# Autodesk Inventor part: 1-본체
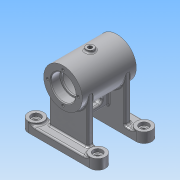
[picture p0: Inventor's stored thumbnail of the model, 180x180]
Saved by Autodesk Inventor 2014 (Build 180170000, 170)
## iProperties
Created: 2015-11
Part Number: 1-본체
Material: 알루미늄 6061
Document SubType Name: Modeling
Designer: 103-23
Density: 2.71 g/cm^3
Appearance: 알루미늄 - 평지
Mass: 358.984 g
Surface Area: 460.1 cm^2
Volume: 132.467 cm^3
Author: 103-23
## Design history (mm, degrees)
sketch "스케치1"
  geometry: L1 (-40, 40)-(40, 40); L2 (40, 20)-(-40, 20); A1 r 10 centre (40, 30) between (40, 20) and (40, 40); A2 r 10 centre (-40, 30) between (-40, 40) and (-40, 20); 1 further point
  constraints: 4 end point, 4 point on circle, 4 tangent, 2 centre point, 1 horizontal, 1 parallel
  dimensions: "d0" = 40 distance from line of L1 point (0, 0); "d1" = 20 distance between parallel lines of L2 L1; "d2" = 80 distance of A1.centre A2.centre; "d3" = 40 horizontal distance of point (0, 0) A2.centre
extrude "돌출1" new body sketch "스케치1" distance "d4" = 10; taper "d5" = 0 deg
node "작업 평면1"
sketch "스케치2"
  geometry: L1 (-35, 68)-(35, 68); L2 (-35, 84)-(-23, 84); L3 (-23, 84)-(-23, 82); L4 (-23, 82)-(-21, 82); L5 (-21, 82)-(-21, 89); L6 (-21, 89)-(21, 89); L7 (21, 89)-(21, 82); L8 (21, 82)-(23, 82); L9 (23, 82)-(23, 84); L10 (23, 84)-(35, 84); L11 (35, 84)-(35, 93); L12 (35, 93)-(-35, 93); L13 (-35, 93)-(-35, 84); 2 further points
  constraints: 26 end point, 10 parallel, 5 collinear, 2 point on line, 1 horizontal, 1 midpoint, 1 perpendicular, 1 vertical alignment
  dimensions: "d7" = 70 distance of L1.start L1.end; "d8" = 68 distance from line of point (0, 0) L1; "d9" = 28 diameter of L4.end L1; "d10" = 32 diameter of L2 L1; "d11" = 42 diameter of L6 L1; "d12" = 50 diameter of L12 L1; "d13" = 12 distance of L2.start L2.end; "d14" = 42 distance of L5.end L6.end
revolve "회전1" sketch "스케치2" stored, may be unused: angle "d15" = 90 deg
sketch "스케치3"
  geometry: L1 (0, 20)-(80, 20) reference; L2 (15, 12)-(65, 12); L3 (65, 12)-(65, 20); L4 (65, 20)-(15, 20); L5 (15, 20)-(15, 12); L6 (15, 12)-(65, 20); L7 (65, 12)-(15, 20); 3 further points
  constraints: 12 end point, 3 midpoint, 2 parallel, 1 collinear, 1 horizontal, 1 perpendicular, 1 vertical alignment
  dimensions: "d17" = 8 distance between parallel lines of L2 L4; "d18" = 50 distance of L2.start L2.end
extrude "돌출2" join sketch "스케치3" stored distance "d19" = 10; taper "d20" = 0 deg
node "작업 평면2"
sketch "스케치4"
  geometry: L1 (-20, 23)-(20, 23); L2 (20, 23)-(20, 45.656); L3 (-20, 45.656)-(-20, 23); L4 (-20, 23)-(20, 43); L5 (20, 23)-(-20, 43); L6 (35, 43)-(-35, 43) reference; L7 (20, 10)-(20, 68) reference; L8 (-20, 10)-(-20, 68) reference; L9 (-20, 45.656)-(20, 45.656); 3 further points
  constraints: 12 end point, 4 point on line, 3 midpoint, 2 perpendicular, 1 collinear, 1 horizontal, 1 parallel, 1 vertical alignment
  dimensions: "d25" = 20 distance between parallel lines of L6 L1; "d26" = 22.65606 distance between parallel lines of L9 L1
extrude "돌출3" join sketch "스케치4" stored distance "d23" = 8; taper "d24" = 0 deg
sketch "스케치5"
  geometry: L1 (43.322, -20)-(23, -20) reference; L2 (36.5, 8)-(36.5, -8); L3 (29.5, -8)-(29.5, 8); A1 r 3.5 centre (33, -8) between (29.5, -8) and (36.5, -8); A2 r 3.5 centre (33, 8) between (36.5, 8) and (29.5, 8); 2 further points
  constraints: 4 end point, 4 point on circle, 4 tangent, 2 centre point, 2 perpendicular, 1 horizontal alignment, 1 midpoint
  dimensions: "d27" = 33 horizontal distance of A1.centre point (0, 0); "d28" = 3.5 radius of A1; "d29" = 23 dimension on A1 A2
extrude "돌출4" cut sketch "스케치5" stored distance "d30" = 8; taper "d31" = 0 deg
sketch "스케치6"
  geometry: C1 r 10 at (-40, 30); C2 r 10 at (40, 30); A1 r 10 centre (40, 30) between (40, 20) and (40, 40) reference; A2 r 10 centre (-40, 30) between (-40, 40) and (-40, 20) reference; 1 further point
  constraints: 2 centre point, 2 coincident, 2 concentric
extrude "돌출5" join sketch "스케치6" distance "d32" = 3; taper "d33" = 0 deg
hole "구멍1" diameter "d36" = 6; stored, may be unused: countersink angle "d40" = 90 deg, drill point angle "d42" = 118 deg; dims "d34" = 10, "d35" = 10, "d37" = 6, "d38" = 12, "d39" = 4, "d41" = 8
hole "구멍2" diameter "d45" = 6; stored, may be unused: countersink angle "d49" = 90 deg, drill point angle "d51" = 118 deg; dims "d43" = 10, "d44" = 10, "d46" = 6, "d47" = 12, "d48" = 4, "d50" = 8
node "작업 평면3"
sketch "스케치7"
  geometry: C1 r 5 at (0, 0); 1 further point
  constraints: 1 centre point, 1 coincident
  dimensions: "d53" = 10 diameter of C1
extrude "돌출6" join sketch "스케치7" stored distance "d54" = 3; taper "d55" = 0 deg
hole "구멍3" diameter "d58" = 5.188; stored, may be unused: countersink angle "d62" = 90 deg, drill point angle "d64" = 118 deg; dims "d56" = 10, "d57" = 10, "d59" = 6, "d60" = 12, "d61" = 4, "d63" = 8
node "작업 평면4"
sketch "스케치8"
  geometry: L1 (-14, 68)-(14, 68); L2 (0, 68)-(14, 43.751); L3 (0, 82)-(0, 54); A1 r 14 centre (0, 68) between (-14, 68) and (14, 68) reference; 1 further point
  constraints: 6 end point, 4 point on circle, 2 midpoint, 1 coincident, 1 horizontal, 1 perpendicular
  dimensions: "d66" = 28 distance of L2.start L2.end; "d67" = 30 deg angle of L3 L2
node "작업 평면5"
sketch "스케치9"
  geometry: C1 r 6 at (0, 0); 2 further points
  constraints: 1 centre point, 1 coincident
  dimensions: "d68" = 12 diameter of C1
extrude "돌출7" join sketch "스케치9" stored distance "d69" = 3; taper "d70" = 0 deg
hole "구멍4" diameter "d73" = 5.188; stored, may be unused: countersink angle "d77" = 90 deg, drill point angle "d79" = 118 deg; dims "d71" = 10, "d72" = 10, "d74" = 6, "d75" = 12, "d76" = 4, "d78" = 8
sketch "스케치10"
  geometry: C1 r 25 at (0, 0) reference; C2 r 16 at (0, 0) reference; A1 r 20 centre (0, 0) between (0, 20) and (0, -20); 3 further points
  constraints: 4 point on circle, 2 horizontal alignment, 2 vertical alignment, 1 centre point, 1 coincident
  dimensions: "d80" = 40 diameter of A1
hole "구멍5" sketch "스케치10" at (0, 20), (0, -20), (20, 0), (-20, 0) diameter "d81" = 3.242; stored, may be unused: countersink angle "d85" = 90 deg, drill point angle "d87" = 118 deg; dims "d82" = 8, "d83" = 12, "d84" = 4, "d86" = 10
node "작업 평면6"
sketch "스케치11"
  geometry: L1 (35, 25)-(-35, 25) reference; L2 (-35, 25)-(-35, -25) reference; 2 further points
  constraints: 1 other
  dimensions: "d88" = 35 distance from line of L2 point (0, 0); "d89" = 25 distance from line of L1 point (0, 0)
feature "엠보싱1" sketch "스케치11" dims "d0" = 40, "d1" = 20, "d2" = 80, "d3" = 40, "d7" = 70, "d8" = 68, "d9" = 28, "d10" = 32, "d11" = 42, "d12" = 50, "d13" = 12, "d14" = 42, "d90" = 0.5, "d91" = 0
fillet "모깎기1" dims "d92" = 0.3, "d93" = 3, "d96" = 2
fillet "모깎기2" dims "d94" = 2
fillet "모깎기5" dims "d98" = 2
fillet "모깎기6" dims "d99" = 2
fillet "모깎기7" dims "d100" = 2
chamfer "모따기1" distance "d101" = 1; stored, may be unused: second distance "d102" = 2, angle "d103" = 45 deg
node "솔리드1"
mirror "대칭1"
mirror "대칭2"
mirror "대칭3"
mirror "대칭4"
other parameters: "d6" = 0, "d21" = 0, "d52" = -96, "d65" = 0
